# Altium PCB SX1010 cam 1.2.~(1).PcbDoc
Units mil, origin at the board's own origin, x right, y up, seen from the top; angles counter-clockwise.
Board outline 1160.61 x 955.91 mil, 2 copper layers (Top Layer, Bottom Layer); 22 components, 18 nets, 45 pads, 0 vias.
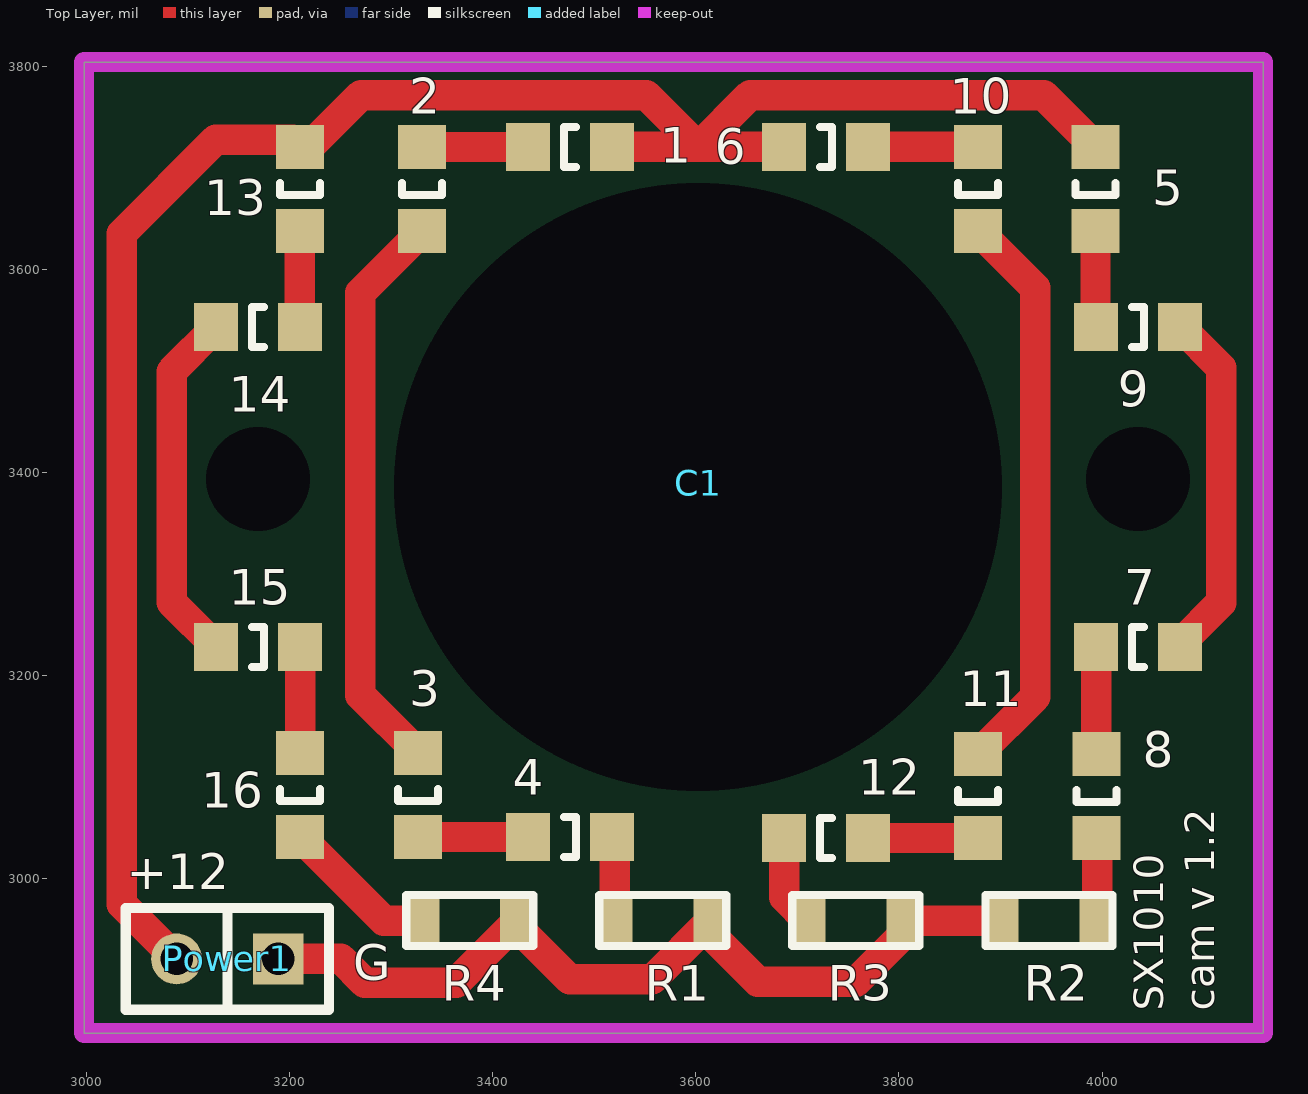
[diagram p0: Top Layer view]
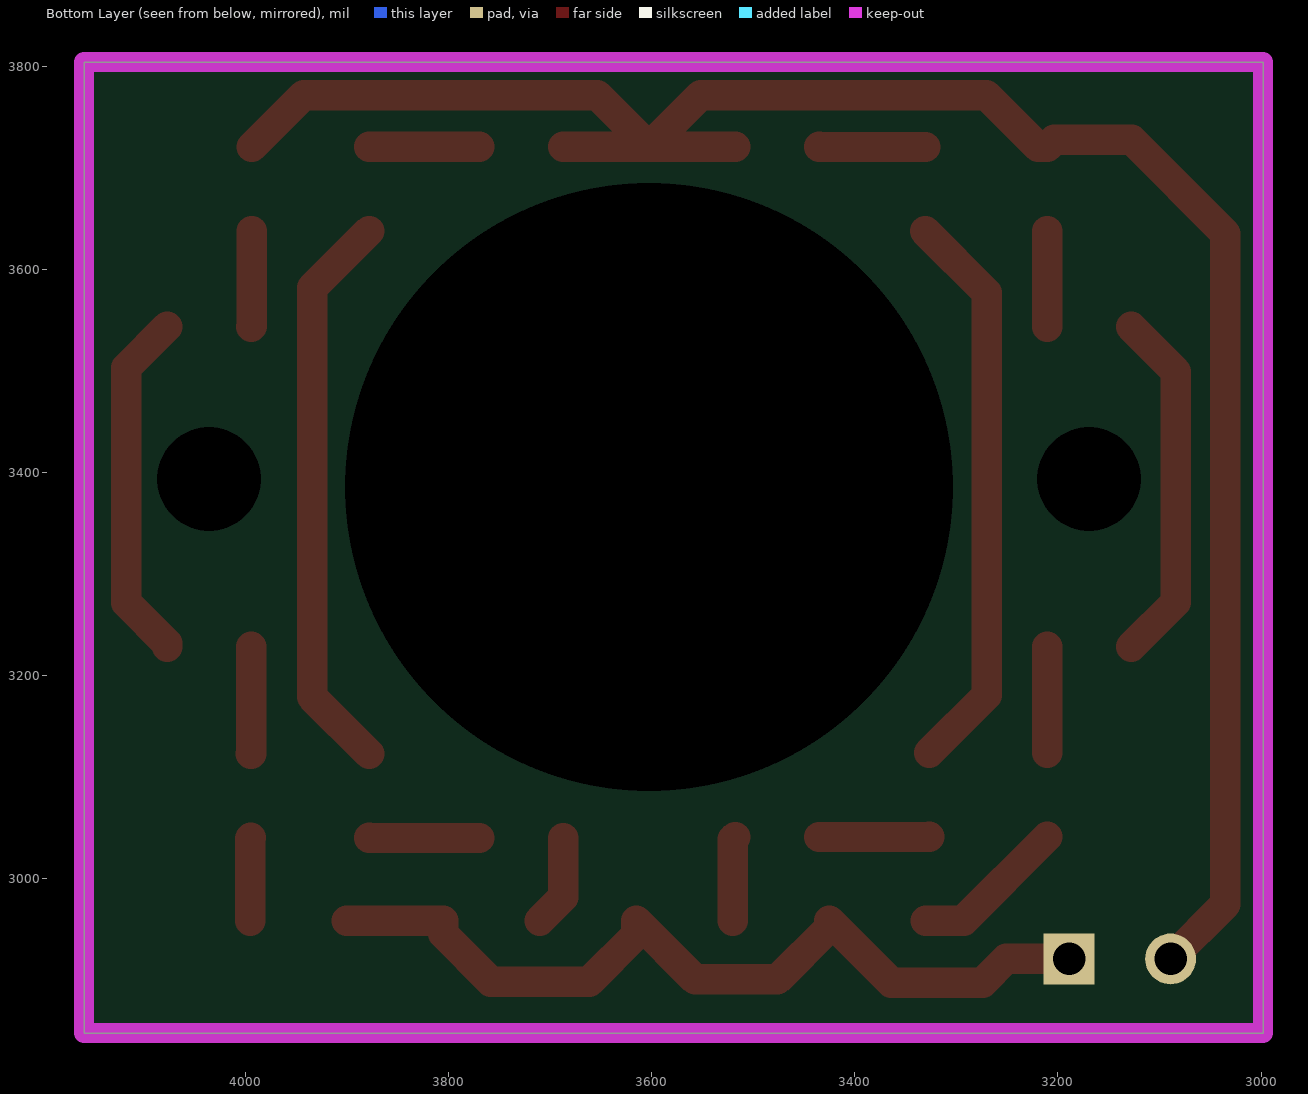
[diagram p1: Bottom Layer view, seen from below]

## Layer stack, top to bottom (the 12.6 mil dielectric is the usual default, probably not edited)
Top Solder: solder mask 0.4, Solder Resist, Dk 3.5
Top Layer: signal copper 1.4
Dielectric 1: dielectric 12.6, FR-4, Dk 4.8
Bottom Layer: signal copper 1.4
Bottom Solder: solder mask 0.4, Solder Resist, Dk 3.5

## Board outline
2997.87,2848.11 2997.87,3804.02 4158.48,3804.02 4158.48,2848.11

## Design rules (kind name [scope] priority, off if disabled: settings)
Clearance [All] p1: gap=7 ignorepadtopadclearanceinfootprint=FALSE
ComponentClearance [All] p1 off: gap=0 collisioncheckmode=3 verticalgap=10 showdistances=FALSE
HoleSize [All] p1: absolutevalues=TRUE maxlimit=600 minlimit=1 maxpercent=80.000 minpercent=20.000
PolygonConnect [All] p1: connectstyle=Relief reliefconductorwidth=10 reliefentries=4 polygonreliefangle="90 Angle" airgapwidth=10
RoutingVias [All] p1: holewidth=28 width=50 viastyle="Through Hole" minholewidth=28 minwidth=50 maxholewidth=28 maxwidth=50
SilkToSolderMaskClearance [IsPad] p1: minsilkscreentomaskgap=0 clearancetoexposedcopper=TRUE
SolderMaskExpansion [All] p1: expansion=4
Width [All] p1: maxlimit=50 minlimit=8 preferedwidth=10
27 further rules are at their usual default settings.

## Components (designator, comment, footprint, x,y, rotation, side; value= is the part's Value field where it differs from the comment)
1 "150080GS75000" 0805_A 3476.38,3720.47 r0 top (schematic designator LED1)
2 "150080GS75000" 0805_A 3330.71,3679.02 r90 top (schematic designator LED2)
3 "150080GS75000" 0805_A 3326.77,3082.68 r90 top (schematic designator LED3)
4 "150080GS75000" 0805_A 3476.38,3041.23 r180 top (schematic designator LED4)
5 "150080GS75000" 0805_A 3993.43,3679.02 r90 top (schematic designator LED5)
6 "150080GS75000" 0805_A 4035.43,3543.31 r180 top (schematic designator LED6)
7 "150080GS75000" 0805_A 4035.43,3228.35 r0 top (schematic designator LED7)
8 "150080GS75000" 0805_A 3994.25,3081.69 r90 top (schematic designator LED8)
9 "150080GS75000" 0805_A 3728.35,3720.47 r180 top (schematic designator LED9)
10 "150080GS75000" 0805_A 3877.95,3679.02 r90 top (schematic designator LED10)
11 "150080GS75000" 0805_A 3877.95,3081.69 r90 top (schematic designator LED11)
12 "150080GS75000" 0805_A 3728.35,3040.24 r0 top (schematic designator LED12)
13 "150080GS75000" 0805_A 3210.41,3679.02 r90 top (schematic designator LED13)
14 "150080GS75000" 0805_A 3169.29,3543.31 r0 top (schematic designator LED14)
15 "150080GS75000" 0805_A 3169.29,3228.35 r180 top (schematic designator LED15)
16 "150080GS75000" 0805_A 3210.41,3082.68 r90 top (schematic designator LED16)
C1 "camera" camera 3598.43,3177.17 r0 top locked
Power1 "CON2_POWER" CON2_POWER 3188.98,2921.26 r180 top
R1 "RES_SMD_0805" RES_SMD_0805 3615.03,2959 r90 top
R2 "RES_SMD_0805" RES_SMD_0805 3900,2959 r270 top
R3 "RES_SMD_0805" RES_SMD_0805 3805.01,2959 r90 top
R4 "RES_SMD_0805" RES_SMD_0805 3425.04,2959 r90 top

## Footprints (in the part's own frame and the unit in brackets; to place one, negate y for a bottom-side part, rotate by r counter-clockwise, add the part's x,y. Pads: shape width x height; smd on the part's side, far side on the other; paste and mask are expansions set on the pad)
0805_A [mm] "Chip LED, 2-Leads, Body 2.0x1.3mm, IPC Medium Density"
  rect 1.1x1.2 smd: 1(-1.05,0) 2(1.05,0)
  silkscreen extent -0.15,-0.5 0.15,0.5, body extent -1,-0.62 1,0.63, height 0.8
camera [mm]
  round 15 hole 15.2: 0(0.1,5.3)
  round 2.4 hole 2.6: 1(11.1,5.5) 2(-10.9,5.5)
CON2_POWER [mil]
  rect 50x50 hole 32: 1(0,0)
  round 50 hole 32: 2(100,0)
  silkscreen extent -50,-50 150,50
RES_SMD_0805 [mil]
  rect 50x35 smd: 1(0,0) 2(0,95)
  silkscreen extent -25,-15 25,110, body extent -25,8 25,86

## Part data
1 2 3 4 5 6 7 8 9 10 11 12 13 14 15 16: "SMD mono-color Chip LED, WL-SMCW, Green", Color=Green

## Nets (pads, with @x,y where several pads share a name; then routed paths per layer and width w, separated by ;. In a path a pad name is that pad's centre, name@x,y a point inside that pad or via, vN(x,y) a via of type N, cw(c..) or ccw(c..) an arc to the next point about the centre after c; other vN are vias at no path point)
+12V: 1.2 5.2 9.2 13.2 Power1.2 | length 1989.6
  Top Layer w30: Power1.2 3035,2975.24 3035,3635 3127.36,3727.36 3203.41,3727.36 13.2 3219.36,3720.36 3270.51,3771.51 3551.32,3771.51 3602.36,3720.47 ; 1.2 3602.36,3720.47 ; 9.2 3602.36,3720.47 ; 5.2 3942.28,3771.51 3653.4,3771.51 3602.36,3720.47
GND: Power1.1 R1.1 R2.1 R3.1 R4.1 | length 863.6
  Top Layer w30: Power1.1 3250.74,2921.26 3274,2898 3364.04,2898 R4.1 3425.04,2951.96 3476,2901 3557.03,2901 R1.1 3615.03,2944.97 3661,2899 3758,2899 3805.01,2946.01 R3.1 R2.1
NetLED1_1: 1.1 2.2 | length 104.4
  Top Layer w30: 2.2 3434.93,3720.36 1.1
NetLED2_1: 2.1 3.2 | length 562.3
  Top Layer w30: 3.2 3270,3180.79 3270,3576.98 2.1
NetLED3_1: 3.1 4.2 | length 108.3
  Top Layer w30: 3.1 3326.88,3041.23 4.2
NetLED4_1: 4.1 R1.2 | length 83.2
  Top Layer w30: 4.1 3520.03,3038.92 R1.2
NetLED5_1: 5.1 6.2 | length 94.7
  Top Layer w30: 5.1 3993.43,3543.97 6.2
NetLED6_1: 6.1 7.2 | length 348.3
  Top Layer w30: 7.2 4076.77,3231.77 4117,3272 4117,3503.08 6.1
NetLED7_1: 7.1 8.2 | length 105.4
  Top Layer w30: 7.1 3994.09,3123.19 8.2
NetLED8_1: 8.1 R2.2 | length 81.7
  Top Layer w30: 8.1 3995,3039.61 R2.2
NetLED9_1: 9.1 10.2 | length 108.3
  Top Layer w30: 9.1 3877.84,3720.47 10.2
NetLED10_1: 10.1 11.2 | length 561.1
  Top Layer w30: 11.2 3934,3179.08 3934,3581.64 10.1
NetLED11_1: 11.1 12.2 | length 108.3
  Top Layer w30: 12.2 3877.84,3040.24 11.1
NetLED12_1: 12.1 R3.2 | length 90.8
  Top Layer w30: 12.1 3687.01,2982.01 R3.2
NetLED13_1: 13.1 14.2 | length 94.5
  Top Layer w30: 13.1 3210.41,3543.53 14.2
NetLED14_1: 14.1 15.2 | length 351.4
  Top Layer w30: 15.2 3084,3272.3 3084,3499.35 14.1
NetLED15_1: 15.1 16.2 | length 104.4
  Top Layer w30: 16.2 3210.63,3124.24 15.1
NetLED16_1: 16.1 R4.2 | length 153.7
  Top Layer w30: 16.1 3292.75,2959 R4.2
pads on no net: C1.0 C1.1 C1.2

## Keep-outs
Keep-Out Layer:
  the board outline again, w19.68

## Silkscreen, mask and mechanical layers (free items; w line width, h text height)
Top Overlay:
  text "+12" at 3040,2990 h35
  text "G" at 3263,2900 h35
  text "SX1010" at 4070,2870 h50 r90
  text "cam v 1.2" at 4120,2870 h50 r90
